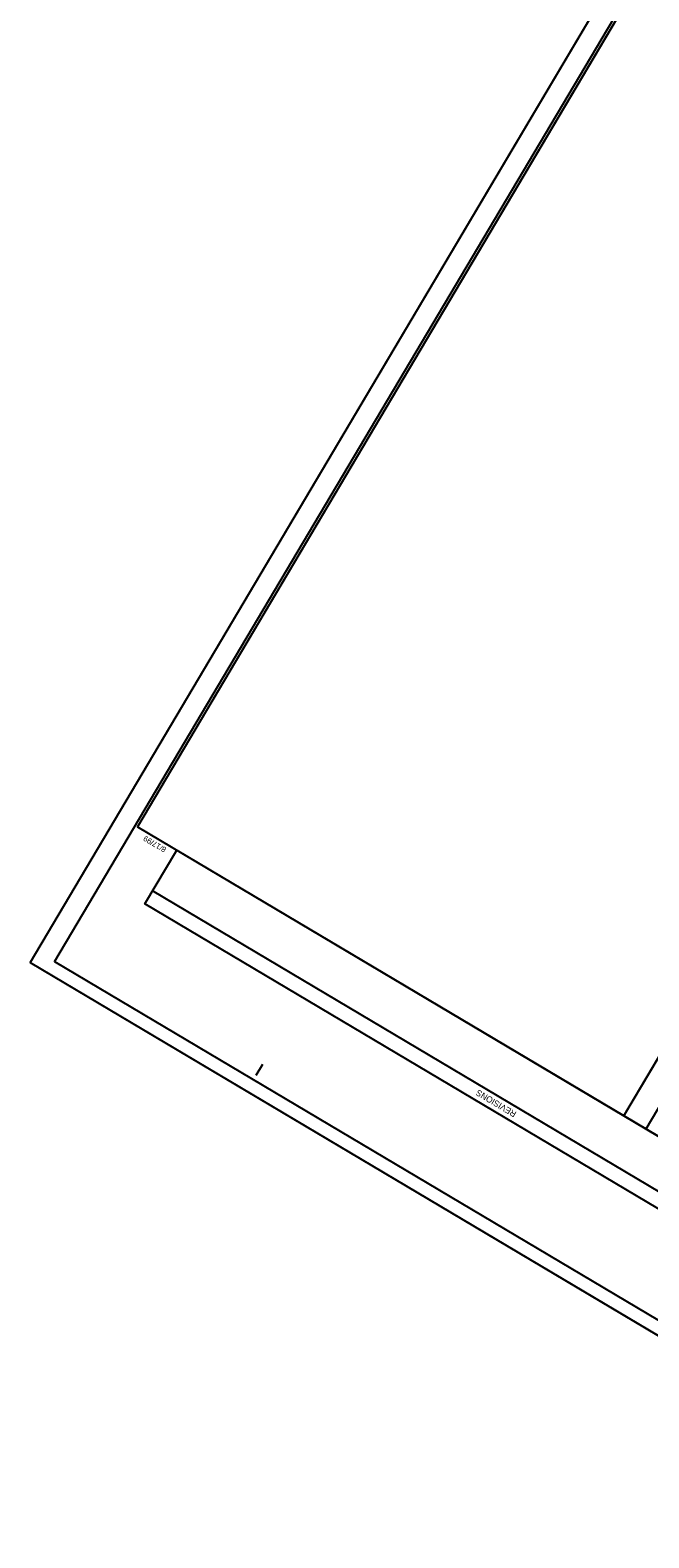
# Model space of a CAD drawing. Extents: x 2137081 to 2142019, y 404041 to 411238.
# Drawn here: x 2140218 to 2140819, y 409034 to 410499 of the extents above; entities that cross this region are included whole.
import ezdxf

# ---------------------------------------------------------------- set-up
doc = ezdxf.new("R2010")
doc.units = 0
for name, color, linetype in [('Sheet Block Revision CELL', 7, 'Continuous'), ('Sheet Clip Boundary CELL', 7, 'Continuous'), ('Sheet Cutting Line CELL', 7, 'Continuous'), ('Sheet DOT Grid CELL', 7, 'Continuous'), ('Sheet Plan And Profile CELL', 7, 'Continuous'), ('Sheet Plot Border Inside CELL', 7, 'Continuous'), ('Sheet Plot Border Outside CELL', 7, 'Continuous'), ('Sheet Profile Grid Major CELL', 7, 'Continuous'), ('Sheet Profile Grid Middle CELL', 7, 'Continuous')]:
    doc.layers.add(name, color=color, linetype=linetype)

msp = doc.modelspace()

# ---------------------------------------------------------------- linework, layer by layer
at = {"layer": 'Sheet Block Revision CELL'}
msp.add_line((2141016.6, 409259.3), (2140336.7, 409662.8), dxfattribs=at)
msp.add_lwpolyline([(2141009.2, 409246.8), (2140329.3, 409650.3), (2140360.2, 409702.4), (2141040.1, 409298.9)], close=True, dxfattribs=at)
at = {"layer": 'Sheet Clip Boundary CELL'}
msp.add_lwpolyline([(2140795, 409444.3), (2141473.2, 410587), (2141453.9, 410598.4), (2141513.1, 410698), (2141213, 410886.1), (2141134.8, 410754.3), (2141040.5, 410810.3), (2140938.2, 410638), (2140883.3, 410670.6), (2140322, 409725)], close=True, dxfattribs=at)
at = {"layer": 'Sheet Cutting Line CELL'}
for p, q in [((2141077, 411041), (2140217.7, 409593.3)), ((2140217.7, 409593.3), (2141159.3, 409034.5))]:
    msp.add_line(p, q, dxfattribs=at)
at = {"layer": 'Sheet DOT Grid CELL'}
msp.add_line((2140795, 409444.3), (2141560.6, 410734.2), dxfattribs=at)
at = {"layer": 'Sheet Plan And Profile CELL'}
msp.add_line((2140437.6, 409483.8), (2140444, 409494.5), dxfattribs=at)
msp.add_lwpolyline([(2141087.6, 411014.9), (2140322, 409725), (2141225, 409189.1), (2141990.6, 410479)], close=True, dxfattribs=at)
at = {"layer": 'Sheet Plot Border Inside CELL'}
msp.add_lwpolyline([(2141148.8, 409055.8), (2141999.1, 410488.5), (2141091.9, 411027), (2140241.5, 409594.3)], close=True, dxfattribs=at)
at = {"layer": 'Sheet Plot Border Outside CELL'}
msp.add_lwpolyline([(2141159.3, 409034.5), (2142018.6, 410482.2), (2141077, 411041), (2140217.7, 409593.3)], close=True, dxfattribs=at)
at = {"layer": 'Sheet Profile Grid Major CELL'}
for points in [[(2140795, 409444.3), (2141560.6, 410734.2)], [(2140795, 409444.3), (2141203.5, 409201.9)]]:
    msp.add_lwpolyline(points, dxfattribs=at)
at = {"layer": 'Sheet Profile Grid Middle CELL'}
msp.add_line((2140816.5, 409431.6), (2141582.1, 410721.5), dxfattribs=at)

# ---------------------------------------------------------------- texts
at = {"layer": 'Sheet Block Revision CELL'}
msp.add_text('REVISIONS', height=6, rotation=149.3093, dxfattribs=at).set_placement((2140691.1, 409447.8))
at = {"layer": 'Sheet Plan And Profile CELL'}
msp.add_text('8/17/99', height=5.25, rotation=149.3093, dxfattribs=at).set_placement((2140350.6, 409704.3))

doc.saveas('drawing.dxf')
